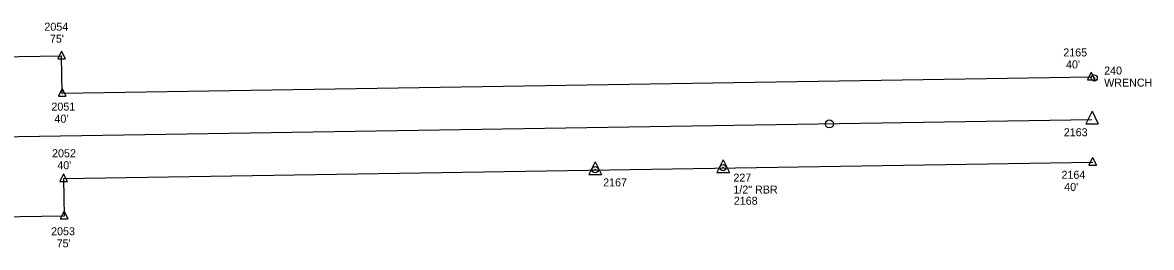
# Model space of a CAD drawing. Extents: x 1799493 to 1803621, y 522869 to 525846.
# Drawn here: x 1802563 to 1803621, y 522884 to 523094 of the extents above; entities that cross this region are included whole.
import ezdxf

# ---------------------------------------------------------------- set-up
doc = ezdxf.new("R2010")
doc.units = 0
for name, color, linetype in [('S_CAL_CORNER', 7, 'Continuous'), ('S_CAL_CORNER_ANNOT', 7, 'Continuous'), ('S_EXIST_ROW', 7, 'Continuous'), ('S_EXIST_ROW_ANNOT', 7, 'Continuous'), ('S_EXISTING_ALIGNMENT', 7, 'Continuous'), ('S_IRON_PIN', 7, 'Continuous'), ('S_IRON_PIN_ANNOT', 7, 'Continuous')]:
    doc.layers.add(name, color=color, linetype=linetype)

msp = doc.modelspace()

# ---------------------------------------------------------------- linework, layer by layer
at = {"layer": 'S_CAL_CORNER'}
for p, q in [((1803565.1, 523011.2), (1803559.2, 522999.4)), ((1803565.1, 523011.2), (1803559.2, 522999.4)), ((1803565.1, 523011.2), (1803570.9, 522999.4)), ((1803565.1, 523011.2), (1803570.9, 522999.4)), ((1803559.2, 522999.4), (1803570.9, 522999.4)), ((1803559.2, 522999.4), (1803570.9, 522999.4)), ((1803099.7, 522963.8), (1803093.8, 522952)), ((1803099.7, 522963.8), (1803105.5, 522952)), ((1803219.5, 522965.7), (1803213.7, 522953.9)), ((1803219.5, 522965.7), (1803225.4, 522953.9)), ((1803093.8, 522952), (1803105.5, 522952)), ((1803213.7, 522953.9), (1803225.4, 522953.9))]:
    msp.add_line(p, q, dxfattribs=at)
at = {"layer": 'S_EXIST_ROW'}
for p, q in [((1802599.8, 523062.9), (1802030.1, 523053.9)), ((1802600.3, 523027.9), (1802599.8, 523062.9)), ((1803564.3, 523043.2), (1802600.3, 523027.9)), ((1803565.6, 522963.2), (1802601.6, 522947.9)), ((1802601.6, 522947.9), (1802602.2, 522912.9)), ((1802602.2, 522912.9), (1802032.5, 522903.9))]:
    msp.add_line(p, q, dxfattribs=at)
at = {"layer": 'S_EXIST_ROW_ANNOT'}
for p, q in [((1802599.8, 523067.6), (1802596.3, 523060.5)), ((1802599.8, 523067.6), (1802603.3, 523060.5)), ((1802596.3, 523060.5), (1802603.3, 523060.5)), ((1802599.8, 523062.9), (1802599.8, 523062.9)), ((1803564.3, 523047.9), (1803560.8, 523040.8)), ((1803564.3, 523047.9), (1803567.8, 523040.8)), ((1803560.8, 523040.8), (1803567.8, 523040.8)), ((1803564.3, 523043.2), (1803564.3, 523043.2)), ((1802600.3, 523032.6), (1802596.8, 523025.5)), ((1802596.8, 523025.5), (1802603.8, 523025.5)), ((1802600.3, 523032.6), (1802603.8, 523025.5)), ((1802600.3, 523027.9), (1802600.3, 523027.9)), ((1803565.6, 522967.9), (1803562.1, 522960.8)), ((1803562.1, 522960.8), (1803569.1, 522960.8)), ((1803565.6, 522967.9), (1803569.1, 522960.8)), ((1803565.6, 522963.2), (1803565.6, 522963.2)), ((1802601.6, 522952.6), (1802598.1, 522945.5)), ((1802601.6, 522952.6), (1802605.1, 522945.5)), ((1802598.1, 522945.5), (1802605.1, 522945.5)), ((1802601.6, 522947.9), (1802601.6, 522947.9)), ((1802602.2, 522917.6), (1802598.6, 522910.5)), ((1802598.6, 522910.5), (1802605.7, 522910.5)), ((1802602.2, 522917.6), (1802605.7, 522910.5)), ((1802602.2, 522912.9), (1802602.2, 522912.9))]:
    msp.add_line(p, q, dxfattribs=at)
for centre, radius in [((1802599.8, 523062.9), 0.12), ((1802599.8, 523062.9), 0.06), ((1803564.3, 523043.2), 0.12), ((1803564.3, 523043.2), 0.06), ((1802600.3, 523027.9), 0.12), ((1802600.3, 523027.9), 0.06), ((1803565.6, 522963.2), 0.06), ((1803565.6, 522963.2), 0.12), ((1802601.6, 522947.9), 0.06), ((1802601.6, 522947.9), 0.12), ((1802602.2, 522912.9), 0.12), ((1802602.2, 522912.9), 0.06)]:
    msp.add_circle(centre, radius, dxfattribs=at)
at = {"layer": 'S_EXISTING_ALIGNMENT'}
msp.add_line((1803565, 523003.2), (1802257, 522982.4), dxfattribs=at)
msp.add_circle((1803319, 522999.4), 3.75, dxfattribs=at)
at = {"layer": 'S_IRON_PIN'}
for centre, radius in [((1803567.1, 523042.4), 2.91), ((1803567.1, 523042.4), 0.411), ((1803567.1, 523042.4), 0.262), ((1803567.1, 523042.4), 0.212), ((1803567.1, 523042.4), 0.145), ((1803567.1, 523042.4), 0.0581), ((1803567.1, 523042.4), 0.0822), ((1803219.4, 522958.3), 2.91), ((1803099.6, 522956.5), 2.91), ((1803099.6, 522956.5), 0.411), ((1803099.6, 522956.5), 0.262), ((1803099.6, 522956.5), 0.212), ((1803099.6, 522956.5), 0.145), ((1803099.6, 522956.5), 0.0581), ((1803099.6, 522956.5), 0.0822), ((1803219.4, 522958.3), 0.411), ((1803219.4, 522958.3), 0.262), ((1803219.4, 522958.3), 0.212), ((1803219.4, 522958.3), 0.145), ((1803219.4, 522958.3), 0.0581), ((1803219.4, 522958.3), 0.0822)]:
    msp.add_circle(centre, radius, dxfattribs=at)

# ---------------------------------------------------------------- texts
at = {"layer": 'S_CAL_CORNER_ANNOT'}
for s, p in [('2163', (1803538.6, 522987.8)), ('2167', (1803107.1, 522940.8)), ('2168', (1803229.5, 522923.6))]:
    msp.add_text(s, height=7.5, dxfattribs=at).set_placement(p)
at = {"layer": 'S_EXIST_ROW_ANNOT'}
for s, p in [('2054', (1802583.7, 523086.7)), ("75'", (1802588.9, 523075.5)), ('2165', (1803538.1, 523062.6)), ("40'", (1803540.7, 523051.4)), ('2051', (1802590.3, 523011.8)), ("40'", (1802593.1, 523000.5)), ('2052', (1802590.9, 522968.1)), ("40'", (1802595.8, 522956.9)), ('2164', (1803536.4, 522947.9)), ("40'", (1803539, 522936.6)), ('2053', (1802590, 522895)), ("75'", (1802595.2, 522883.7))]:
    msp.add_text(s, height=7.5, dxfattribs=at).set_placement(p)
at = {"layer": 'S_IRON_PIN_ANNOT'}
for s, p in [('240', (1803576.4, 523045.6)), ('WRENCH', (1803576.4, 523034.3)), ('227', (1803229.1, 522945.3)), ('1/2" RBR', (1803229.1, 522934.1))]:
    msp.add_text(s, height=7.5, dxfattribs=at).set_placement(p)

doc.saveas('drawing.dxf')
